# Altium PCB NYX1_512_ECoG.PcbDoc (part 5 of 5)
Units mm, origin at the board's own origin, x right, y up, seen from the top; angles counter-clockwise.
Board outline 46.64 x 13 mm, 4 copper layers (metal 2, via, metal1, electrodes), stack 0.007 mm thick; 9 components, 547 nets, 1871 pads, 0 vias.
Unrouted connection lines stored in the file: 652.
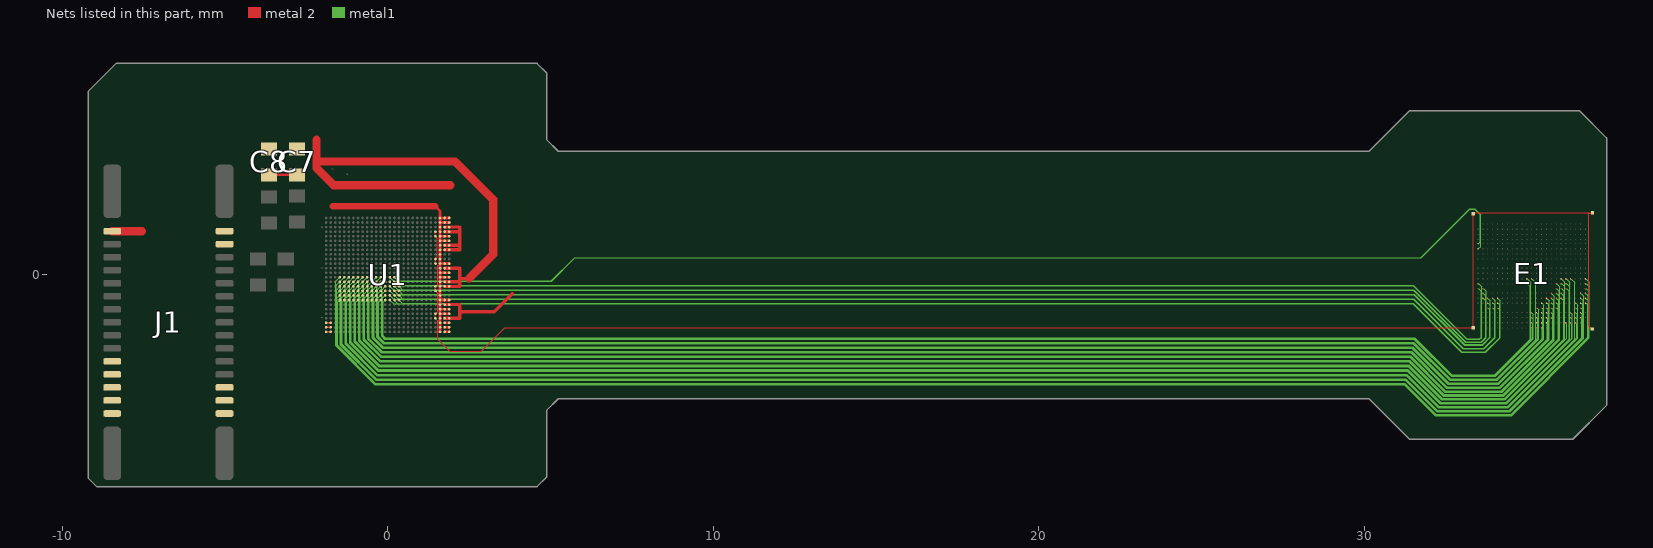
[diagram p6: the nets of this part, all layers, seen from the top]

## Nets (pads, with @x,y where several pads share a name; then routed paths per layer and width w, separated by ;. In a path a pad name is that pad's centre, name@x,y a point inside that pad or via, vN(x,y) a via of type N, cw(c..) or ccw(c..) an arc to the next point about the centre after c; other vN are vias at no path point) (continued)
el430: E1.364 pad.34@33.641,-0.725 U1.M16 | length 35.4
  metal 2 w0.012: pad.34@33.641,-0.725 E1.364@33.641,-0.706
  metal1 w0.005: U1.M16@0.35,-0.349 0.447,-0.446 30.141,-0.446 31.515,-0.446 33.113,-2.044 33.592,-2.044 33.721,-1.914 33.721,-0.786 33.66,-0.725 pad.34@33.641,-0.725
el431: E1.411 pad.34@33.791,-1.025 U1.M17 | length 35.2
  metal 2 w0.012: pad.34@33.791,-1.025 E1.411@33.791,-1.006
  metal1 w0.005: U1.M17@0.35,-0.489 0.447,-0.586 3.141,-0.586 31.528,-0.586 33.076,-2.134 33.629,-2.134 33.851,-1.912 33.851,-1.066 33.81,-1.025 pad.34@33.791,-1.025
el432: E1.412 pad.34@33.941,-1.025 U1.M18 | length 35.4
  metal 2 w0.012: pad.34@33.941,-1.025 E1.412@33.941,-1.006
  metal1 w0.005: U1.M18@0.35,-0.629 0.447,-0.726 3.141,-0.726 31.513,-0.726 33.031,-2.245 33.674,-2.245 34.001,-1.917 34.001,-1.066 33.96,-1.025 pad.34@33.941,-1.025
el433: E1.413 pad.34@34.091,-1.025 U1.M19 | length 35.6
  metal 2 w0.012: pad.34@34.091,-1.025 E1.413@34.091,-1.006
  metal1 w0.005: U1.M19@0.35,-0.769 0.447,-0.866 3.141,-0.866 30.141,-0.866 31.497,-0.866 32.987,-2.356 33.717,-2.356 34.151,-1.923 34.151,-1.066 34.11,-1.025 pad.34@34.091,-1.025
el434: E1.133 pad.34@33.491,0.814 U1.N14 | length 35.5
  metal 2 w0.012: E1.133@33.491,0.794 pad.34@33.491,0.814
  metal1 w0.005: U1.N14@0.21,-0.069 0.317,-0.176 5.033,-0.176 5.741,0.532 30.141,0.532 31.737,0.532 33.237,2.032 33.387,2.032 33.571,1.849 33.571,0.874 33.51,0.814 pad.34@33.491,0.814
el435: E1.317 pad.34@33.491,-0.425 U1.N15 | length 35.7
  metal 2 w0.012: pad.34@33.491,-0.425 E1.317@33.491,-0.406
  metal1 w0.005: U1.N15@0.21,-0.209 0.317,-0.316 5.05,-0.316 31.499,-0.316 33.145,-1.963 33.547,-1.963 33.591,-1.918 33.591,-0.506 33.51,-0.425 pad.34@33.491,-0.425
el436: E1.341 pad.34@33.641,-0.575 U1.N16 | length 35.7
  metal 2 w0.012: pad.34@33.641,-0.575 E1.341@33.641,-0.556
  metal1 w0.005: U1.N16@0.21,-0.349 0.317,-0.456 30.141,-0.456 31.511,-0.456 33.109,-2.054 33.596,-2.054 33.731,-1.918 33.731,-0.646 33.66,-0.575 pad.34@33.641,-0.575
el437: E1.388 pad.34@33.791,-0.875 U1.N17 | length 35.5
  metal 2 w0.012: pad.34@33.791,-0.875 E1.388@33.791,-0.856
  metal1 w0.005: U1.N17@0.21,-0.489 0.317,-0.596 3.141,-0.596 31.524,-0.596 33.071,-2.144 33.633,-2.144 33.861,-1.916 33.861,-0.926 33.81,-0.875 pad.34@33.791,-0.875
el438: E1.389 pad.34@33.941,-0.875 U1.N18 | length 35.7
  metal 2 w0.012: pad.34@33.941,-0.875 E1.389@33.941,-0.856
  metal1 w0.005: U1.N18@0.21,-0.629 0.317,-0.736 3.141,-0.736 31.508,-0.736 33.027,-2.255 33.678,-2.255 34.011,-1.921 34.011,-0.926 33.96,-0.875 pad.34@33.941,-0.875
el439: E1.390 pad.34@34.091,-0.875 U1.N19 | length 35.9
  metal 2 w0.012: pad.34@34.091,-0.875 E1.390@34.091,-0.856
  metal1 w0.005: U1.N19@0.21,-0.769 0.317,-0.876 3.141,-0.876 30.141,-0.876 31.493,-0.876 32.983,-2.366 33.722,-2.366 34.161,-1.927 34.161,-0.926 34.11,-0.875 pad.34@34.091,-0.875
el440: E1.110 pad.34@33.491,0.964 U1.P14 | length 35.5
  metal 2 w0.012: E1.110@33.491,0.944 pad.34@33.491,0.964
  metal1 w0.005: U1.P14@0.07,-0.069 0.188,-0.186 5.037,-0.186 5.745,0.522 30.141,0.522 31.742,0.522 33.242,2.022 33.383,2.022 33.561,1.845 33.561,1.014 33.51,0.964 pad.34@33.491,0.964
el441: E1.294 pad.34@33.491,-0.275 U1.P15 | length 36
  metal 2 w0.012: pad.34@33.491,-0.275 E1.294@33.491,-0.256
  metal1 w0.005: U1.P15@0.07,-0.209 0.188,-0.326 5.054,-0.326 31.494,-0.326 33.141,-1.973 33.551,-1.973 33.601,-1.923 33.601,-0.366 33.51,-0.275 pad.34@33.491,-0.275
el442: E1.318 pad.34@33.641,-0.425 U1.P16 | length 36
  metal 2 w0.012: pad.34@33.641,-0.425 E1.318@33.641,-0.406
  metal1 w0.005: U1.P16@0.07,-0.349 0.188,-0.466 31.507,-0.466 33.105,-2.064 33.6,-2.064 33.741,-1.923 33.741,-0.506 33.66,-0.425 pad.34@33.641,-0.425
el443: E1.365 pad.34@33.791,-0.725 U1.P17 | length 35.8
  metal 2 w0.012: pad.34@33.791,-0.725 E1.365@33.791,-0.706
  metal1 w0.005: U1.P17@0.07,-0.489 0.188,-0.606 3.141,-0.606 31.52,-0.606 33.067,-2.154 33.637,-2.154 33.871,-1.92 33.871,-0.786 33.81,-0.725 pad.34@33.791,-0.725
el444: E1.366 pad.34@33.941,-0.725 U1.P18 | length 36
  metal 2 w0.012: pad.34@33.941,-0.725 E1.366@33.941,-0.706
  metal1 w0.005: U1.P18@0.07,-0.629 0.188,-0.746 3.141,-0.746 31.504,-0.746 33.023,-2.265 33.682,-2.265 34.021,-1.925 34.021,-0.786 33.96,-0.725 pad.34@33.941,-0.725
el445: E1.367 pad.34@34.091,-0.725 U1.P19 | length 36.2
  metal 2 w0.012: pad.34@34.091,-0.725 E1.367@34.091,-0.706
  metal1 w0.005: U1.P19@0.07,-0.769 0.188,-0.886 3.141,-0.886 30.141,-0.886 31.489,-0.886 32.979,-2.376 33.726,-2.376 34.171,-1.931 34.171,-0.786 34.11,-0.725 pad.34@34.091,-0.725
el446: E1.443 pad.34@35.141,-1.175 U1.R14 | length 39.1
  metal 2 w0.012: pad.34@35.141,-1.175 E1.443@35.141,-1.156
  metal1 w0.005: U1.R14@-0.07,-0.069 -0.188,-0.186 -0.188,-1.883 -0.099,-1.971 29.641,-1.971 31.523,-1.971 32.668,-3.117 34.032,-3.117 35.191,-1.958 35.191,-1.206 35.16,-1.175 pad.34@35.141,-1.175
el447: E1.466 pad.34@35.141,-1.325 U1.R15 | length 38.7
  metal 2 w0.012: pad.34@35.141,-1.325 E1.466@35.141,-1.306
  metal1 w0.005: U1.R15@-0.07,-0.209 -0.178,-0.316 -0.178,-1.879 -0.095,-1.961 31.527,-1.961 32.672,-3.107 34.028,-3.107 35.181,-1.954 35.181,-1.346 35.16,-1.325 pad.34@35.141,-1.325
el448: E1.488 pad.34@35.141,-1.475 U1.R16 | length 38.4
  metal 2 w0.012: pad.34@35.141,-1.475 E1.488@35.141,-1.456
  metal1 w0.005: U1.R16@-0.07,-0.349 -0.168,-0.446 -0.168,-1.875 -0.091,-1.951 31.531,-1.951 32.676,-3.097 34.024,-3.097 35.171,-1.95 35.171,-1.505 pad.34@35.141,-1.475
el449: E1.508 pad.34@35.141,-1.625 U1.R17 | length 38.1
  metal 2 w0.012: pad.34@35.141,-1.625 E1.508@35.141,-1.606
  metal1 w0.005: U1.R17@-0.07,-0.489 -0.158,-0.576 -0.158,-1.871 -0.087,-1.941 31.535,-1.941 32.68,-3.087 34.02,-3.087 35.161,-1.945 35.161,-1.645 pad.34@35.141,-1.625
el450: E1.281 pad.34@34.991,-0.125 U1.R18 | length 39.4
  metal 2 w0.012: pad.34@34.991,-0.125 E1.281@34.991,-0.106
  metal1 w0.005: U1.R18@-0.07,-0.629 -0.148,-0.706 -0.148,-1.866 -0.083,-1.931 31.539,-1.931 32.685,-3.077 34.016,-3.077 35.111,-1.981 35.111,-0.226 35.01,-0.125 pad.34@34.991,-0.125
el451: E1.304 pad.34@34.991,-0.275 U1.R19 | length 39.1
  metal 2 w0.012: pad.34@34.991,-0.275 E1.304@34.991,-0.256
  metal1 w0.005: U1.R19@-0.07,-0.769 -0.138,-0.836 -0.138,-1.862 -0.079,-1.921 31.543,-1.921 32.689,-3.067 34.012,-3.067 35.101,-1.977 35.101,-0.366 35.01,-0.275 pad.34@34.991,-0.275
el452: E1.421 pad.34@35.291,-1.025 U1.T14 | length 39.6
  metal 2 w0.012: pad.34@35.291,-1.025 E1.421@35.291,-1.006
  metal1 w0.005: U1.T14@-0.21,-0.069 -0.328,-0.186 -0.328,-1.913 -0.129,-2.111 30.693,-2.111 31.491,-2.111 32.618,-3.238 34.081,-3.238 35.351,-1.968 35.351,-1.066 35.31,-1.025 pad.34@35.291,-1.025
el453: E1.444 pad.34@35.291,-1.175 U1.T15 | length 39.3
  metal 2 w0.012: pad.34@35.291,-1.175 E1.444@35.291,-1.156
  metal1 w0.005: U1.T15@-0.21,-0.209 -0.318,-0.316 -0.318,-1.909 -0.125,-2.101 30.697,-2.101 31.495,-2.101 32.622,-3.228 34.077,-3.228 35.341,-1.963 35.341,-1.206 35.31,-1.175 pad.34@35.291,-1.175
el454: E1.467 pad.34@35.291,-1.325 U1.T16 | length 39
  metal 2 w0.012: pad.34@35.291,-1.325 E1.467@35.291,-1.306
  metal1 w0.005: U1.T16@-0.21,-0.349 -0.308,-0.446 -0.308,-1.904 -0.121,-2.091 30.701,-2.091 31.499,-2.091 32.626,-3.218 34.073,-3.218 35.331,-1.959 35.331,-1.346 35.31,-1.325 pad.34@35.291,-1.325
el455: E1.489 pad.34@35.291,-1.475 U1.T17 | length 38.6
  metal 2 w0.012: pad.34@35.291,-1.475 E1.489@35.291,-1.456
  metal1 w0.005: U1.T17@-0.21,-0.489 -0.298,-0.576 -0.298,-1.9 -0.117,-2.081 30.705,-2.081 31.503,-2.081 32.63,-3.208 34.069,-3.208 35.321,-1.955 35.321,-1.505 pad.34@35.291,-1.475
el456: E1.509 pad.34@35.291,-1.625 U1.T18 | length 38.3
  metal 2 w0.012: pad.34@35.291,-1.625 E1.509@35.291,-1.606
  metal1 w0.005: U1.T18@-0.21,-0.629 -0.288,-0.706 -0.288,-1.896 -0.113,-2.071 30.709,-2.071 31.508,-2.071 32.634,-3.198 34.064,-3.198 35.311,-1.951 35.311,-1.645 pad.34@35.291,-1.625
el457: E1.282 pad.34@35.141,-0.125 U1.T19 | length 39.7
  metal 2 w0.012: pad.34@35.141,-0.125 E1.282@35.141,-0.106
  metal1 w0.005: U1.T19@-0.21,-0.769 -0.278,-0.836 -0.278,-1.892 -0.108,-2.061 31.512,-2.061 32.637,-3.187 34.061,-3.187 35.261,-1.987 35.261,-0.226 35.16,-0.125 pad.34@35.141,-0.125
el458: E1.399 pad.34@35.441,-0.875 U1.U14 | length 40.2
  metal 2 w0.012: pad.34@35.441,-0.875 E1.399@35.441,-0.856
  metal1 w0.005: U1.U14@-0.35,-0.069 -0.468,-0.186 -0.468,-1.942 -0.158,-2.252 31.46,-2.252 32.567,-3.358 34.13,-3.358 35.511,-1.977 35.511,-0.926 35.46,-0.875 pad.34@35.441,-0.875
el459: E1.422 pad.34@35.441,-1.025 U1.U15 | length 39.9
  metal 2 w0.012: pad.34@35.441,-1.025 E1.422@35.441,-1.006
  metal1 w0.005: U1.U15@-0.35,-0.209 -0.458,-0.316 -0.458,-1.938 -0.154,-2.242 31.464,-2.242 32.571,-3.348 34.126,-3.348 35.501,-1.973 35.501,-1.066 35.46,-1.025 pad.34@35.441,-1.025
el460: E1.445 pad.34@35.441,-1.175 U1.U16 | length 39.6
  metal 2 w0.012: pad.34@35.441,-1.175 E1.445@35.441,-1.156
  metal1 w0.005: U1.U16@-0.35,-0.349 -0.448,-0.446 -0.448,-1.934 -0.15,-2.232 31.468,-2.232 32.575,-3.338 34.122,-3.338 35.491,-1.969 35.491,-1.206 35.46,-1.175 pad.34@35.441,-1.175
el461: E1.468 pad.34@35.441,-1.325 U1.U17 | length 39.2
  metal 2 w0.012: pad.34@35.441,-1.325 E1.468@35.441,-1.306
  metal1 w0.005: U1.U17@-0.35,-0.489 -0.438,-0.576 -0.438,-1.93 -0.146,-2.222 31.472,-2.222 32.579,-3.328 34.117,-3.328 35.481,-1.965 35.481,-1.346 35.46,-1.325 pad.34@35.441,-1.325
el462: E1.490 pad.34@35.441,-1.475 U1.U18 | length 38.9
  metal 2 w0.012: pad.34@35.441,-1.475 E1.490@35.441,-1.456
  metal1 w0.005: U1.U18@-0.35,-0.629 -0.428,-0.706 -0.428,-1.926 -0.142,-2.212 31.478,-2.212 32.584,-3.318 34.114,-3.318 35.471,-1.961 35.471,-1.505 pad.34@35.441,-1.475
el463: E1.510 pad.34@35.441,-1.625 U1.U19 | length 38.6
  metal 2 w0.012: pad.34@35.441,-1.625 E1.510@35.441,-1.606
  metal1 w0.005: U1.U19@-0.35,-0.769 -0.418,-0.836 -0.418,-1.922 -0.138,-2.202 30.567,-2.202 31.482,-2.202 32.588,-3.308 34.11,-3.308 35.461,-1.957 35.461,-1.645 pad.34@35.441,-1.625
el464: E1.377 pad.34@35.591,-0.725 U1.V14 | length 40.8
  metal 2 w0.012: pad.34@35.591,-0.725 E1.377@35.591,-0.706
  metal1 w0.005: U1.V14@-0.49,-0.069 -0.608,-0.186 -0.608,-1.972 -0.189,-2.391 30.633,-2.391 ; 30.637,-2.391 31.43,-2.391 32.517,-3.478 34.18,-3.478 35.671,-1.987 35.671,-0.786 35.61,-0.725 pad.34@35.591,-0.725
el465: E1.400 pad.34@35.591,-0.875 U1.V15 | length 40.5
  metal 2 w0.012: pad.34@35.591,-0.875 E1.400@35.591,-0.856
  metal1 w0.005: U1.V15@-0.49,-0.209 -0.598,-0.316 -0.598,-1.968 -0.185,-2.381 30.637,-2.381 ; 30.641,-2.381 31.434,-2.381 32.521,-3.468 34.175,-3.468 35.661,-1.983 35.661,-0.926 35.61,-0.875 pad.34@35.591,-0.875
el466: E1.423 pad.34@35.591,-1.025 U1.V16 | length 40.1
  metal 2 w0.012: pad.34@35.591,-1.025 E1.423@35.591,-1.006
  metal1 w0.005: U1.V16@-0.49,-0.349 -0.588,-0.446 -0.588,-1.964 -0.18,-2.371 31.438,-2.371 32.525,-3.458 34.171,-3.458 35.651,-1.979 35.651,-1.066 35.61,-1.025 pad.34@35.591,-1.025
el467: E1.446 pad.34@35.591,-1.175 U1.V17 | length 39.8
  metal 2 w0.012: pad.34@35.591,-1.175 E1.446@35.591,-1.156
  metal1 w0.005: U1.V17@-0.49,-0.489 -0.578,-0.576 -0.578,-1.96 -0.176,-2.361 31.442,-2.361 32.529,-3.448 34.167,-3.448 35.641,-1.975 35.641,-1.206 35.61,-1.175 pad.34@35.591,-1.175
el468: E1.469 pad.34@35.591,-1.325 U1.V18 | length 39.5
  metal 2 w0.012: pad.34@35.591,-1.325 E1.469@35.591,-1.306
  metal1 w0.005: U1.V18@-0.49,-0.629 -0.568,-0.706 -0.568,-1.956 -0.172,-2.351 31.446,-2.351 32.533,-3.438 34.163,-3.438 35.631,-1.97 35.631,-1.346 35.61,-1.325 pad.34@35.591,-1.325
el469: E1.491 pad.34@35.591,-1.475 U1.V19 | length 39.1
  metal 2 w0.012: pad.34@35.591,-1.475 E1.491@35.591,-1.456
  metal1 w0.005: U1.V19@-0.49,-0.769 -0.558,-0.836 -0.558,-1.952 -0.168,-2.341 31.45,-2.341 32.538,-3.428 34.159,-3.428 35.621,-1.966 35.621,-1.505 pad.34@35.591,-1.475
el470: E1.355 pad.34@35.741,-0.575 U1.W14 | length 41.4
  metal 2 w0.012: pad.34@35.741,-0.575 E1.355@35.741,-0.556
  metal1 w0.005: U1.W14@-0.63,-0.069 -0.748,-0.186 -0.748,-2.002 -0.218,-2.531 30.603,-2.531 ; 30.607,-2.531 31.4,-2.531 32.467,-3.599 34.229,-3.599 35.831,-1.997 35.831,-0.646 35.76,-0.575 pad.34@35.741,-0.575
el471: E1.378 pad.34@35.741,-0.725 U1.W15 | length 41
  metal 2 w0.012: pad.34@35.741,-0.725 E1.378@35.741,-0.706
  metal1 w0.005: U1.W15@-0.63,-0.209 -0.738,-0.316 -0.738,-1.998 -0.214,-2.521 31.404,-2.521 32.471,-3.588 34.225,-3.588 35.821,-1.993 35.821,-0.786 35.76,-0.725 pad.34@35.741,-0.725
el472: E1.401 pad.34@35.741,-0.875 U1.W16 | length 40.7
  metal 2 w0.012: pad.34@35.741,-0.875 E1.401@35.741,-0.856
  metal1 w0.005: U1.W16@-0.63,-0.349 -0.728,-0.446 -0.728,-1.994 -0.21,-2.511 31.408,-2.511 32.475,-3.578 34.221,-3.578 35.811,-1.988 35.811,-0.926 35.76,-0.875 pad.34@35.741,-0.875
el473: E1.424 pad.34@35.741,-1.025 U1.W17 | length 40.4
  metal 2 w0.012: pad.34@35.741,-1.025 E1.424@35.741,-1.006
  metal1 w0.005: U1.W17@-0.63,-0.489 -0.718,-0.576 -0.718,-1.99 -0.206,-2.501 31.412,-2.501 32.48,-3.568 34.217,-3.568 35.801,-1.984 35.801,-1.066 35.76,-1.025 pad.34@35.741,-1.025
el474: E1.447 pad.34@35.741,-1.175 U1.W18 | length 40
  metal 2 w0.012: pad.34@35.741,-1.175 E1.447@35.741,-1.156
  metal1 w0.005: U1.W18@-0.63,-0.629 -0.708,-0.706 -0.708,-1.985 -0.202,-2.491 31.416,-2.491 32.484,-3.558 34.213,-3.558 35.791,-1.98 35.791,-1.206 35.76,-1.175 pad.34@35.741,-1.175
el475: E1.470 pad.34@35.741,-1.325 U1.W19 | length 39.7
  metal 2 w0.012: pad.34@35.741,-1.325 E1.470@35.741,-1.306
  metal1 w0.005: U1.W19@-0.63,-0.769 -0.698,-0.836 -0.698,-1.981 -0.198,-2.481 31.42,-2.481 32.488,-3.548 34.209,-3.548 35.781,-1.976 35.781,-1.346 35.76,-1.325 pad.34@35.741,-1.325
el476: E1.310 pad.34@35.891,-0.275 U1.Y14 | length 42.1
  metal 2 w0.012: pad.34@35.891,-0.275 E1.310@35.891,-0.256
  metal1 w0.005: U1.Y14@-0.77,-0.069 -0.888,-0.186 -0.888,-2.032 -0.248,-2.671 31.37,-2.671 32.417,-3.719 34.279,-3.719 36.001,-1.997 36.001,-0.366 35.91,-0.275 pad.34@35.891,-0.275
el477: E1.333 pad.34@35.891,-0.425 U1.Y15 | length 41.8
  metal 2 w0.012: pad.34@35.891,-0.425 E1.333@35.891,-0.406
  metal1 w0.005: U1.Y15@-0.77,-0.209 -0.878,-0.316 -0.878,-2.028 -0.244,-2.661 31.374,-2.661 32.422,-3.709 34.275,-3.709 35.991,-1.992 35.991,-0.506 35.91,-0.425 pad.34@35.891,-0.425
el478: E1.356 pad.34@35.891,-0.575 U1.Y16 | length 41.4
  metal 2 w0.012: pad.34@35.891,-0.575 E1.356@35.891,-0.556
  metal1 w0.005: U1.Y16@-0.77,-0.349 -0.868,-0.446 -0.868,-2.023 -0.24,-2.651 31.378,-2.651 32.426,-3.699 34.271,-3.699 35.981,-1.988 35.981,-0.646 35.91,-0.575 pad.34@35.891,-0.575
el479: E1.379 pad.34@35.891,-0.725 U1.Y17 | length 41.1
  metal 2 w0.012: pad.34@35.891,-0.725 E1.379@35.891,-0.706
  metal1 w0.005: U1.Y17@-0.77,-0.489 -0.858,-0.576 -0.858,-2.019 -0.236,-2.641 31.382,-2.641 32.43,-3.689 34.267,-3.689 35.971,-1.984 35.971,-0.786 35.91,-0.725 pad.34@35.891,-0.725
el480: E1.402 pad.34@35.891,-0.875 U1.Y18 | length 40.8
  metal 2 w0.012: pad.34@35.891,-0.875 E1.402@35.891,-0.856
  metal1 w0.005: U1.Y18@-0.77,-0.629 -0.848,-0.706 -0.848,-2.015 -0.232,-2.631 31.387,-2.631 32.434,-3.679 34.262,-3.679 35.961,-1.98 35.961,-0.926 35.91,-0.875 pad.34@35.891,-0.875
el481: E1.425 pad.34@35.891,-1.025 U1.Y19 | length 40.5
  metal 2 w0.012: pad.34@35.891,-1.025 E1.425@35.891,-1.006
  metal1 w0.005: U1.Y19@-0.77,-0.769 -0.838,-0.836 -0.838,-2.011 -0.227,-2.621 31.391,-2.621 32.438,-3.669 34.258,-3.669 35.951,-1.976 35.951,-1.066 35.91,-1.025 pad.34@35.891,-1.025
el482: E1.495 pad.34@36.191,-1.475 U1.AA14 | length 41.3
  metal 2 w0.012: pad.34@36.191,-1.475 E1.495@36.191,-1.456
  metal1 w0.005: U1.AA14@-0.91,-0.069 -1.028,-0.186 -1.028,-2.061 -0.278,-2.811 3.141,-2.811 29.629,-2.811 31.34,-2.811 32.369,-3.84 34.328,-3.84 36.221,-1.946 36.221,-1.505 pad.34@36.191,-1.475
el483: E1.288 pad.34@36.041,-0.125 U1.AA15 | length 42.5
  metal 2 w0.012: pad.34@36.041,-0.125 E1.288@36.041,-0.106
  metal1 w0.005: U1.AA15@-0.91,-0.209 -1.018,-0.316 -1.018,-2.057 -0.274,-2.801 31.344,-2.801 32.372,-3.829 34.325,-3.829 36.161,-1.992 36.161,-0.226 36.06,-0.125 pad.34@36.041,-0.125
el484: E1.311 pad.34@36.041,-0.275 U1.AA16 | length 42.2
  metal 2 w0.012: pad.34@36.041,-0.275 E1.311@36.041,-0.256
  metal1 w0.005: U1.AA16@-0.91,-0.349 -1.008,-0.446 -1.008,-2.053 -0.27,-2.791 30.551,-2.791 31.349,-2.791 32.376,-3.819 34.32,-3.819 36.151,-1.988 36.151,-0.366 36.06,-0.275 pad.34@36.041,-0.275
el485: E1.334 pad.34@36.041,-0.425 U1.AA17 | length 41.9
  metal 2 w0.012: pad.34@36.041,-0.425 E1.334@36.041,-0.406
  metal1 w0.005: U1.AA17@-0.91,-0.489 -0.998,-0.576 -0.998,-2.049 -0.265,-2.781 30.555,-2.781 ; 30.551,-2.781 31.353,-2.781 32.38,-3.809 34.316,-3.809 36.141,-1.984 36.141,-0.506 36.06,-0.425 pad.34@36.041,-0.425
el486: E1.357 pad.34@36.041,-0.575 U1.AA18 | length 41.5
  metal 2 w0.012: pad.34@36.041,-0.575 E1.357@36.041,-0.556
  metal1 w0.005: U1.AA18@-0.91,-0.629 -0.988,-0.706 -0.988,-2.045 -0.261,-2.771 30.559,-2.771 31.357,-2.771 32.384,-3.799 34.312,-3.799 36.131,-1.98 36.131,-0.646 36.06,-0.575 pad.34@36.041,-0.575
el487: E1.380 pad.34@36.041,-0.725 U1.AA19 | length 41.2
  metal 2 w0.012: pad.34@36.041,-0.725 E1.380@36.041,-0.706
  metal1 w0.005: U1.AA19@-0.91,-0.769 -0.978,-0.836 -0.978,-2.041 -0.257,-2.761 30.563,-2.761 ; 30.559,-2.761 31.361,-2.761 32.388,-3.789 34.308,-3.789 36.121,-1.976 36.121,-0.786 36.06,-0.725 pad.34@36.041,-0.725
el488: E1.451 pad.34@36.341,-1.175 U1.AB14 | length 42.1
  metal 2 w0.012: pad.34@36.341,-1.175 E1.451@36.341,-1.156
  metal1 w0.005: U1.AB14@-1.05,-0.069 -1.168,-0.186 -1.168,-2.091 -0.308,-2.951 3.141,-2.951 29.641,-2.951 30.481,-2.951 31.311,-2.951 32.319,-3.96 34.377,-3.96 36.391,-1.946 36.391,-1.206 36.36,-1.175 pad.34@36.341,-1.175
el489: E1.474 pad.34@36.341,-1.325 U1.AB15 | length 41.7
  metal 2 w0.012: pad.34@36.341,-1.325 E1.474@36.341,-1.306
  metal1 w0.005: U1.AB15@-1.05,-0.209 -1.158,-0.316 -1.158,-2.087 -0.304,-2.941 3.141,-2.941 29.641,-2.941 30.485,-2.941 31.315,-2.941 32.323,-3.95 34.373,-3.95 36.381,-1.942 36.381,-1.346 ; pad.34@36.341,-1.325 36.36,-1.325 36.381,-1.345
el490: E1.496 pad.34@36.341,-1.475 U1.AB16 | length 41.4
  metal 2 w0.012: pad.34@36.341,-1.475 E1.496@36.341,-1.456
  metal1 w0.005: U1.AB16@-1.05,-0.349 -1.148,-0.446 -1.148,-2.083 -0.299,-2.931 3.141,-2.931 29.641,-2.931 31.319,-2.931 32.327,-3.94 34.369,-3.94 36.371,-1.938 36.371,-1.505 pad.34@36.341,-1.475
el491: E1.289 pad.34@36.191,-0.125 U1.AB17 | length 42.6
  metal 2 w0.012: pad.34@36.191,-0.125 E1.289@36.191,-0.106
  metal1 w0.005: U1.AB17@-1.05,-0.489 -1.138,-0.576 -1.138,-2.079 -0.295,-2.921 3.141,-2.921 29.641,-2.921 31.323,-2.921 32.331,-3.93 34.365,-3.93 36.311,-1.984 36.311,-0.226 36.21,-0.125 pad.34@36.191,-0.125
el492: E1.312 pad.34@36.191,-0.275 U1.AB18 | length 42.3
  metal 2 w0.012: pad.34@36.191,-0.275 E1.312@36.191,-0.256
  metal1 w0.005: U1.AB18@-1.05,-0.629 -1.128,-0.706 -1.128,-2.075 -0.291,-2.911 3.141,-2.911 29.641,-2.911 31.327,-2.911 32.336,-3.92 34.361,-3.92 36.301,-1.979 36.301,-0.366 36.21,-0.275 pad.34@36.191,-0.275
el493: E1.335 pad.34@36.191,-0.425 U1.AB19 | length 41.9
  metal 2 w0.012: pad.34@36.191,-0.425 E1.335@36.191,-0.406
  metal1 w0.005: U1.AB19@-1.05,-0.769 -1.118,-0.836 -1.118,-2.07 -0.287,-2.901 3.141,-2.901 29.641,-2.901 31.331,-2.901 32.34,-3.91 34.357,-3.91 36.291,-1.975 36.291,-0.506 36.21,-0.425 pad.34@36.191,-0.425
el494: E1.406 pad.34@36.491,-0.875 U1.AC14 | length 42.8
  metal 2 w0.012: pad.34@36.491,-0.875 E1.406@36.491,-0.856
  metal1 w0.005: U1.AC14@-1.19,-0.069 -1.308,-0.186 -1.308,-2.121 -0.337,-3.091 3.141,-3.091 29.641,-3.091 31.281,-3.091 32.27,-4.08 34.426,-4.08 36.561,-1.946 36.561,-0.926 36.51,-0.875 pad.34@36.491,-0.875
el495: E1.429 pad.34@36.491,-1.025 U1.AC15 | length 42.5
  metal 2 w0.012: pad.34@36.491,-1.025 E1.429@36.491,-1.006
  metal1 w0.005: U1.AC15@-1.19,-0.209 -1.298,-0.316 -1.298,-2.117 -0.333,-3.081 3.141,-3.081 29.641,-3.081 31.285,-3.081 32.274,-4.07 34.422,-4.07 36.551,-1.942 36.551,-1.066 36.51,-1.025 pad.34@36.491,-1.025
el496: E1.452 pad.34@36.491,-1.175 U1.AC16 | length 42.1
  metal 2 w0.012: pad.34@36.491,-1.175 E1.452@36.491,-1.156
  metal1 w0.005: U1.AC16@-1.19,-0.349 -1.288,-0.446 -1.288,-2.113 -0.329,-3.071 3.141,-3.071 29.641,-3.071 31.289,-3.071 32.278,-4.06 34.418,-4.06 36.541,-1.937 36.541,-1.206 36.51,-1.175 pad.34@36.491,-1.175
el497: E1.475 pad.34@36.491,-1.325 U1.AC17 | length 41.8
  metal 2 w0.012: pad.34@36.491,-1.325 E1.475@36.491,-1.306
  metal1 w0.005: U1.AC17@-1.19,-0.489 -1.278,-0.576 -1.278,-2.109 -0.325,-3.061 3.141,-3.061 29.641,-3.061 31.293,-3.061 32.283,-4.05 34.414,-4.05 36.531,-1.933 36.531,-1.346 36.51,-1.325 pad.34@36.491,-1.325
el498: E1.497 pad.34@36.491,-1.475 U1.AC18 | length 41.5
  metal 2 w0.012: pad.34@36.491,-1.475 E1.497@36.491,-1.456
  metal1 w0.005: U1.AC18@-1.19,-0.629 -1.268,-0.706 -1.268,-2.104 -0.321,-3.051 3.141,-3.051 29.641,-3.051 31.297,-3.051 32.287,-4.04 34.41,-4.04 36.521,-1.929 36.521,-1.505 pad.34@36.491,-1.475
el499: E1.290 pad.34@36.341,-0.125 U1.AC19 | length 42.7
  metal 2 w0.012: pad.34@36.341,-0.125 E1.290@36.341,-0.106
  metal1 w0.005: U1.AC19@-1.19,-0.769 -1.258,-0.836 -1.258,-2.1 -0.317,-3.041 31.301,-3.041 32.29,-4.03 34.406,-4.03 36.461,-1.975 36.461,-0.226 36.36,-0.125 pad.34@36.341,-0.125
el500: E1.361 pad.34@36.641,-0.575 U1.AD14 | length 43.5
  metal 2 w0.012: pad.34@36.641,-0.575 E1.361@36.641,-0.556
  metal1 w0.005: U1.AD14@-1.33,-0.069 -1.448,-0.186 -1.448,-2.151 -0.367,-3.231 31.251,-3.231 32.22,-4.201 34.476,-4.201 36.731,-1.945 36.731,-0.646 36.66,-0.575 pad.34@36.641,-0.575
el501: E1.384 pad.34@36.641,-0.725 U1.AD15 | length 43.2
  metal 2 w0.012: pad.34@36.641,-0.725 E1.384@36.641,-0.706
  metal1 w0.005: U1.AD15@-1.33,-0.209 -1.438,-0.316 -1.438,-2.147 -0.363,-3.221 31.255,-3.221 32.225,-4.191 34.472,-4.191 36.721,-1.941 36.721,-0.786 36.66,-0.725 pad.34@36.641,-0.725
el502: E1.407 pad.34@36.641,-0.875 U1.AD16 | length 42.9
  metal 2 w0.012: pad.34@36.641,-0.875 E1.407@36.641,-0.856
  metal1 w0.005: U1.AD16@-1.33,-0.349 -1.428,-0.446 -1.428,-2.142 -0.359,-3.211 31.259,-3.211 32.229,-4.181 34.468,-4.181 36.711,-1.937 36.711,-0.926 36.66,-0.875 pad.34@36.641,-0.875
el503: E1.430 pad.34@36.641,-1.025 U1.AD17 | length 42.5
  metal 2 w0.012: pad.34@36.641,-1.025 E1.430@36.641,-1.006
  metal1 w0.005: U1.AD17@-1.33,-0.489 -1.418,-0.576 -1.418,-2.138 -0.355,-3.201 31.263,-3.201 32.233,-4.171 34.464,-4.171 36.701,-1.933 36.701,-1.066 36.66,-1.025 pad.34@36.641,-1.025
el504: E1.453 pad.34@36.641,-1.175 U1.AD18 | length 42.2
  metal 2 w0.012: pad.34@36.641,-1.175 E1.453@36.641,-1.156
  metal1 w0.005: U1.AD18@-1.33,-0.629 -1.408,-0.706 -1.408,-2.134 -0.351,-3.191 31.268,-3.191 32.237,-4.161 34.459,-4.161 36.691,-1.929 36.691,-1.206 36.66,-1.175 pad.34@36.641,-1.175
el505: E1.476 pad.34@36.641,-1.325 U1.AD19 | length 41.9
  metal 2 w0.012: pad.34@36.641,-1.325 E1.476@36.641,-1.306
  metal1 w0.005: U1.AD19@-1.33,-0.769 -1.398,-0.836 -1.398,-2.13 -0.346,-3.181 31.272,-3.181 32.241,-4.151 34.455,-4.151 36.681,-1.925 36.681,-1.346 36.66,-1.325 pad.34@36.641,-1.325
el506: E1.293 pad.34@36.791,-0.125 U1.AE14 | length 44.4
  metal 2 w0.012: pad.34@36.791,-0.125 E1.293@36.791,-0.106
  metal1 w0.005: U1.AE14@-1.47,-0.069 -1.588,-0.186 -1.588,-2.18 -0.397,-3.371 31.221,-3.371 32.171,-4.321 34.526,-4.321 36.911,-1.935 36.911,-0.226 36.81,-0.125 pad.34@36.791,-0.125
el507: E1.316 pad.34@36.791,-0.275 U1.AE15 | length 44.1
  metal 2 w0.012: pad.34@36.791,-0.275 E1.316@36.791,-0.256
  metal1 w0.005: U1.AE15@-1.47,-0.209 -1.578,-0.316 -1.578,-2.176 -0.393,-3.361 3.141,-3.361 29.554,-3.361 31.225,-3.361 32.175,-4.311 34.522,-4.311 36.901,-1.931 36.901,-0.366 36.81,-0.275 pad.34@36.791,-0.275
el508: E1.339 pad.34@36.791,-0.425 U1.AE16 | length 43.8
  metal 2 w0.012: pad.34@36.791,-0.425 E1.339@36.791,-0.406
  metal1 w0.005: U1.AE16@-1.47,-0.349 -1.568,-0.446 -1.568,-2.172 -0.389,-3.351 3.141,-3.351 29.558,-3.351 31.23,-3.351 32.179,-4.301 34.517,-4.301 36.891,-1.927 36.891,-0.506 36.81,-0.425 pad.34@36.791,-0.425
el509: E1.362 pad.34@36.791,-0.575 U1.AE17 | length 43.4
  metal 2 w0.012: pad.34@36.791,-0.575 E1.362@36.791,-0.556
  metal1 w0.005: U1.AE17@-1.47,-0.489 -1.558,-0.576 -1.558,-2.168 -0.384,-3.341 3.141,-3.341 29.562,-3.341 31.234,-3.341 32.183,-4.291 34.513,-4.291 36.881,-1.923 36.881,-0.646 36.81,-0.575 pad.34@36.791,-0.575
el510: E1.385 pad.34@36.791,-0.725 U1.AE18 | length 43.1
  metal 2 w0.012: pad.34@36.791,-0.725 E1.385@36.791,-0.706
  metal1 w0.005: U1.AE18@-1.47,-0.629 -1.548,-0.706 -1.548,-2.164 -0.38,-3.331 3.141,-3.331 29.566,-3.331 31.238,-3.331 32.187,-4.281 34.509,-4.281 36.871,-1.919 36.871,-0.786 36.81,-0.725 pad.34@36.791,-0.725
el511: E1.408 pad.34@36.791,-0.875 U1.AE19 | length 42.8
  metal 2 w0.012: pad.34@36.791,-0.875 E1.408@36.791,-0.856
  metal1 w0.005: U1.AE19@-1.47,-0.769 -1.538,-0.836 -1.538,-2.16 -0.376,-3.321 3.141,-3.321 29.571,-3.321 31.242,-3.321 32.191,-4.271 34.505,-4.271 36.861,-1.915 36.861,-0.926 36.81,-0.875 pad.34@36.791,-0.875
GND: J1.28
MUX01_CS: J1.27
MUX01_MISO: J1.23
MUX01_MOSI: J1.25
MUX01_RES: J1.29
MUX01_SCLK: J1.21
NetU1_A24: U1.A24 U1.B24 | length 0.1
  metal 2 w0.08: U1.B24@1.75,-1.469 U1.A24@1.89,-1.469
NetU1_A25: U1.A25 U1.B25 | length 0.1
  metal 2 w0.08: U1.B25@1.75,-1.609 U1.A25@1.89,-1.609
NetU1_A26: U1.A26 U1.B26 | length 0.1
  metal 2 w0.08: U1.B26@1.75,-1.749 U1.A26@1.89,-1.749
NetU1_AG24: U1.AG24 U1.AH24 | length 0.1
  metal 2 w0.05: U1.AH24@-1.89,-1.469 U1.AG24@-1.75,-1.469
NetU1_AG25: U1.AG25 U1.AH25 | length 0.1
  metal 2 w0.05: U1.AH25@-1.89,-1.609 U1.AG25@-1.75,-1.609
NetU1_AG26: U1.AG26 U1.AH26 | length 0.1
  metal 2 w0.05: U1.AH26@-1.89,-1.749 U1.AG26@-1.75,-1.749
REF: pad.28 U1.D4 U1.D5 U1.D10 U1.D11 U1.D16 U1.D17 U1.D22 U1.D23 | length 46.6
  metal 2 w0.02: U1.D4@1.47,1.331 U1.D5@1.47,1.191 1.47,1.188 1.529,1.129 1.529,0.55 U1.D10@1.47,0.491 U1.D11@1.47,0.351 1.537,0.284 1.537,-0.282 U1.D16@1.47,-0.349 U1.D17@1.47,-0.489 1.541,-0.56 1.541,-1.126 1.479,-1.189 U1.D22@1.47,-1.189 U1.D23@1.47,-1.329 1.47,-1.337 1.54,-1.407 1.54,-1.979 1.905,-2.344 2.879,-2.344 3.604,-1.619 pad.28@33.341,-1.619 pad.28@33.341,1.877 33.372,1.908 pad.28@37.005,1.908 36.988,1.891 36.908,1.891 36.896,1.88 36.896,-1.575 36.937,-1.616 36.957,-1.616 pad.28@36.997,-1.656
VCC_1V8: J1.30
VCC_2V5: C7.1 C8.1 J1.1 U1.A3 U1.A4 U1.A7 U1.A8 U1.A12 U1.A15 U1.A16 U1.A20 U1.A23 U1.B3 U1.B4 U1.B7 U1.B8 U1.B12 U1.B15 U1.B16 U1.B20 U1.B23 | length 22.8
  metal 2 w0.1: C8.1@-3.644,3.87 C8.1@-3.624,3.85 ; U1.B23@1.75,-1.329 U1.A23@1.89,-1.329 2.215,-1.329 2.215,-1.131 ; U1.B20@1.75,-0.909 U1.A20@1.89,-0.909 2.215,-0.909 2.215,-1.131 ; U1.B16@1.75,-0.35 1.89,-0.35 2.215,-0.35 2.215,-0.21 ; U1.B15@1.75,-0.21 1.89,-0.21 2.215,-0.21 ; U1.B12@1.75,0.211 U1.A12@1.89,0.211 2.215,0.21 2.215,-0.108 ; U1.B8@1.75,0.771 U1.A8@1.89,0.771 2.215,0.771 2.215,0.911 ; U1.B7@1.75,0.911 U1.A7@1.89,0.911 2.215,0.911 ; U1.B4@1.75,1.331 U1.A4@1.89,1.331 2.215,1.331 ; U1.B3@1.75,1.471 U1.A3@1.89,1.471 2.211,1.471 ; 2.215,1.466 2.215,1.331 ; 2.501,-0.108 2.215,-0.108 ; 3.829,-0.573 3.271,-1.131 2.215,-1.131 ; 2.215,-0.21 2.215,-0.108 ; 2.215,0.911 2.215,1.331
  metal 2 w0.254: J1.1@-8.459,1.346 -7.549,1.346 -7.544,1.341 ; -2.187,4.155 -2.187,3.488 ; 1.933,2.758 -1.66,2.758 -2.187,3.285 -2.187,3.488 ; 2.501,-0.108 3.241,0.632 3.241,2.319 2.072,3.488 -2.187,3.488
VDD_5V: J1.26
VSSA: C7.2 C8.2 J1.2 J1.4 U1.A1 U1.A2 U1.A5 U1.A6 U1.A11 U1.A13 U1.A14 U1.A19 U1.A21 U1.A22 U1.B1 U1.B2 U1.B5 U1.B6 U1.B11 U1.B13 U1.B14 U1.B19 U1.B21 U1.B22 U1.C1 U1.C2 U1.C3 U1.C4 U1.C5 U1.C6 U1.C7 U1.C8 U1.C9 U1.C10 U1.C11 U1.C12 U1.C13 U1.C14 U1.C15 U1.C16 U1.C17 U1.C18 U1.C19 U1.C20 U1.C21 U1.C22 U1.C23 U1.C24 U1.C25 U1.C26 | length 10.9
  metal 2 w0.08: C8.2@-3.698,3.088 -3.686,3.076 C7.2@-2.786,3.076 C7.2@-2.732,3.076 ; 1.465,2.105 1.61,1.96 U1.C1@1.61,1.751 ; U1.C26@1.61,-1.749 U1.C25@1.61,-1.609 U1.C24@1.61,-1.469 U1.C23@1.61,-1.329 U1.C22@1.61,-1.189 ; U1.A22@1.89,-1.189 U1.B22@1.75,-1.189 U1.C22@1.61,-1.189 ; U1.A21@1.89,-1.049 U1.B21@1.75,-1.049 U1.C21@1.61,-1.049 ; U1.A19@1.89,-0.769 1.75,-0.769 U1.C19@1.61,-0.769 ; U1.A14@1.89,-0.069 U1.B14@1.75,-0.069 U1.C14@1.61,-0.069 ; U1.A13@1.89,0.071 U1.B13@1.75,0.071 U1.C13@1.61,0.071 ; U1.A11@1.89,0.351 U1.B11@1.75,0.351 U1.C11@1.61,0.351 ; U1.A6@1.89,1.051 U1.B6@1.75,1.051 U1.C6@1.61,1.051 ; U1.A5@1.89,1.191 U1.B5@1.75,1.191 U1.C5@1.61,1.191 ; U1.A2@1.89,1.611 1.75,1.611 U1.C2@1.61,1.611 ; U1.A1@1.89,1.751 U1.B1@1.75,1.751 U1.C1@1.61,1.751 ; U1.C22@1.61,-1.189 U1.C21@1.61,-1.049 ; U1.C21@1.61,-1.049 U1.C20@1.61,-0.909 U1.C19@1.61,-0.769 ; U1.C19@1.61,-0.769 U1.C18@1.61,-0.629 U1.C17@1.61,-0.489 U1.C16@1.61,-0.349 U1.C15@1.61,-0.209 U1.C14@1.61,-0.069 ; U1.C14@1.61,-0.069 U1.C13@1.61,0.071 ; U1.C13@1.61,0.071 U1.C12@1.61,0.211 U1.C11@1.61,0.351 ; U1.C11@1.61,0.351 U1.C10@1.61,0.491 U1.C9@1.61,0.631 U1.C8@1.61,0.771 U1.C7@1.61,0.911 U1.C6@1.61,1.051 ; U1.C6@1.61,1.051 U1.C5@1.61,1.191 ; U1.C5@1.61,1.191 U1.C4@1.61,1.331 U1.C3@1.61,1.471 U1.C2@1.61,1.611 ; U1.C2@1.61,1.611 U1.C1@1.61,1.751
  metal 2 w0.1: C8.2@-3.698,3.07 C8.2@-3.644,3.07
  metal 2 w0.2: -1.687,2.105 1.465,2.105
pads on no net: J1.31 J1.32 J1.33 J1.34 U1.AA1 U1.AA26 U1.AB1 U1.AB26 U1.AC1 U1.AC26 U1.AD1 U1.AD26 U1.AE1 U1.AE26 U1.D1 U1.D26 U1.E1 U1.E4 U1.E5 U1.E10 U1.E11 U1.E16 U1.E17 U1.E22 U1.E23 U1.E26 U1.F1 U1.F26 U1.G1 U1.G26 U1.H1 U1.H26 U1.J1 U1.J26 U1.K1 U1.K26 U1.L1 U1.L26 U1.M1 U1.M26 U1.N1 U1.N26 U1.P1 U1.P26 U1.R1 U1.R26 U1.T1 U1.T26 U1.U1 U1.U26 U1.V1 U1.V26 U1.W1 U1.W26 U1.Y1 U1.Y26

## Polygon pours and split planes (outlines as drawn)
VSSA on metal 2 "NONET_L-01_P-001" (solid, pour order 10): 1.799,2.561 1.799,2.558 1.899,2.459 1.899,1.752 1.61,1.752 1.445,2.561
VSSA on metal 2 "NONET_L-01_P-001" (solid, pour order 1): -4.653,2.095 -4.654,2.094 -4.654,1.665 -4.775,1.544 -5.237,1.544 -5.387,1.394 -5.387,0.884 -5.345,0.842 -4.83,0.842 -4.084,1.588 -4.084,2.483 -3.819,2.744 -2.541,2.744 -1.764,1.967 1.649,1.967 1.649,2.357 1.445,2.561 -1.809,2.561 -2.722,3.474 -4.653,3.474
VCC_2V5 on metal 2 "NONET_L-01_P-001" (solid, pour order 0): -6.877,1.094 -6.29,1.681 -6.29,2.963 -5.231,4.023 2.557,4.023 4.241,2.338 4.241,0.294 3.091,-0.856 2.215,-0.856 2.215,-1.378 3.468,-1.378 5.041,0.194 5.041,3.553 3.102,5.473 -6.98,5.473 -7.759,4.694 -7.759,1.094
VCC_2V5 on metal 2 "NONET_L-01_P-001" (solid, pour order 35): 1.864,2.885 1.984,2.885 2.262,2.606 2.262,1.423 2.11,1.423 2.075,1.458 2.078,1.462 2.078,2.456 1.903,2.631
VCC_2V5 on metal 2 "NONET_L-01_P-001" (solid, pour order 34): 2.138,0.262 2.701,0.262 2.709,0.254 2.709,-0.172 2.482,-0.399 2.142,-0.399
VCC_2V5 on metal 2 "NONET_L-01_P-001" (solid, pour order 12): -5.658,3.675 -2.257,3.675 -2.257,4.129 -2.324,4.196 -5.205,4.196
DVSS on metal 2 "NONET_L-01_P-001" (solid, pour order 28): -5.016,-3.169 -2.255,-3.169 -1.807,-2.641 -1.807,-2.571 -1.807,-2.038 -2.874,-2.038 -3.776,-2.94 -5.001,-2.94
DVSS on metal 2 "NONET_L-01_P-001" (solid, pour order 20): -1.807,-2.13 -1.983,-2.306 -3.142,-2.306 -2.649,-1.813 -1.66,-1.813 -1.807,-1.96
DVSS on metal 2 "NONET_L-01_P-001" (solid, pour order 27): -5.423,-0.941 -4.958,-0.941 -4.694,-0.678 -4.12,-0.104 -2.453,-0.104 -3.521,-1.172 -5.479,-1.172 -5.479,-1.078
DVSS_BOT on metal1 "NONET_L-01_P-001" (solid, pour order 24): -7.52,0.83 -7.524,0.826 -8.455,0.826 -8.455,0.999 -8.396,1.058 -6.877,1.058 -6.806,1.129 -6.806,2.095 -6.141,2.095 -6.141,0.922 -6.235,0.83 -6.251,0.83
DVDD_1V2 on metal1 "NONET_L-01_P-001" (solid, pour order 26): -5.502,0.662 -4.831,0.662 -4.778,0.715 -2.268,0.715 -2.258,0.725 -2.244,0.711 -2.244,0.214 -4.314,0.214 -4.532,0.432 -5.036,0.432
DVDD_1V2_BOT on metal1 "NONET_L-01_P-001" (solid, pour order 25): -8.338,0.433 -8.375,0.47 -8.192,0.653 -6.141,0.653 -5.966,0.828 -5.966,1.749 -5.781,1.934 -5.78,1.933 -2.257,1.933 -2.207,1.883 -2.207,1.583 -2.392,1.398 -4.027,1.398 -4.191,1.562 -5.725,1.562 -5.725,0.676 -5.946,0.433 -6.053,0.433
DVSS_BOT on metal1 "NONET_L-01_P-001" (solid, pour order 8): -2.023,2.548 -2.023,2.626 -6.529,2.626 -6.806,2.399 -6.806,2.06 -2.32,2.06

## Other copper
metal 2:
  region: 203 vertices and 1 holes, not listed, extent -2.114,-5.449 -1.673,-4.982
  region: 362 vertices and 0 holes, not listed, extent -3.251,-5.45 -2.754,-4.828
  region: 207 vertices and 1 holes, not listed, extent -0.736,-5.449 -0.298,-4.982
  region: 276 vertices and 0 holes, not listed, extent -2.736,-5.45 -2.302,-4.982
  region: 496 vertices and 2 holes, not listed, extent -4.088,-5.545 -3.4,-4.722
  region: -1.638,-5.318 -1.637,-4.995 -1.633,-4.992 -1.625,-4.99 -1.535,-4.992 -1.531,-4.995 -1.53,-5 -1.529,-5.005 -1.53,-5.043 -1.527,-5.046 -1.524,-5.045 -1.518,-5.039 -1.516,-5.038 -1.512,-5.035 -1.511,-5.033 -1.503,-5.025 -1.501,-5.024 -1.498,-5.021 -1.497,-5.019 -1.495,-5.017 -1.485,-5.012 -1.481,-5.007 -1.466,-4.999 -1.464,-4.997 -1.458,-4.995 -1.434,-4.986 -1.429,-4.985 -1.423,-4.984 -1.409,-4.983 -1.379,-4.982 -1.376,-4.984 -1.353,-4.985 -1.336,-4.993 -1.327,-4.994 -1.318,-5 -1.309,-5.005 -1.304,-5.007 -1.302,-5.01 -1.299,-5.011 -1.293,-5.017 -1.29,-5.019 -1.284,-5.025 -1.283,-5.026 -1.281,-5.028 -1.276,-5.033 -1.275,-5.035 -1.273,-5.037 -1.268,-5.045 -1.264,-5.05 -1.26,-5.057 -1.258,-5.065 -1.256,-5.066 -1.252,-5.074 -1.25,-5.083 -1.249,-5.092 -1.245,-5.105 -1.243,-5.109 -1.242,-5.117 -1.241,-5.122 -1.24,-5.143 -1.241,-5.436 -1.245,-5.44 -1.25,-5.441 -1.35,-5.44 -1.355,-5.436 -1.357,-5.428 -1.356,-5.417 -1.357,-5.167 -1.358,-5.163 -1.36,-5.148 -1.365,-5.135 -1.367,-5.13 -1.369,-5.123 -1.373,-5.117 -1.379,-5.112 -1.383,-5.104 -1.393,-5.097 -1.4,-5.093 -1.408,-5.091 -1.415,-5.09 -1.422,-5.088 -1.426,-5.087 -1.445,-5.086 -1.448,-5.087 -1.459,-5.091 -1.467,-5.092 -1.471,-5.094 -1.477,-5.099 -1.486,-5.104 -1.489,-5.107 -1.49,-5.109 -1.499,-5.118 -1.504,-5.126 -1.506,-5.129 -1.507,-5.131 -1.51,-5.136 -1.512,-5.145 -1.519,-5.16 -1.52,-5.175 -1.521,-5.196 -1.522,-5.437 -1.526,-5.441 -1.532,-5.443 -1.535,-5.441 -1.632,-5.44 -1.636,-5.437 -1.638,-5.432 -1.638,-5.319
  region: 257 vertices and 0 holes, not listed, extent -1.207,-5.45 -0.774,-4.982
  region: -2.266,-5.107 -2.267,-4.999 -2.264,-4.994 -2.262,-4.992 -2.254,-4.99 -2.154,-4.992 -2.15,-4.995 -2.149,-5.003 -2.15,-5.436 -2.154,-5.44 -2.158,-5.441 -2.262,-5.44 -2.265,-5.437 -2.267,-5.43 -2.266,-5.408 -2.266,-5.108
  region: -2.256,-4.829 -2.252,-4.825 -2.25,-4.824 -2.244,-4.821 -2.232,-4.818 -2.223,-4.816 -2.218,-4.815 -2.21,-4.813 -2.199,-4.815 -2.193,-4.817 -2.186,-4.818 -2.179,-4.82 -2.174,-4.821 -2.168,-4.823 -2.164,-4.826 -2.16,-4.83 -2.152,-4.835 -2.149,-4.838 -2.144,-4.846 -2.14,-4.85 -2.136,-4.858 -2.135,-4.865 -2.131,-4.874 -2.13,-4.879 -2.13,-4.886 -2.131,-4.889 -2.132,-4.9 -2.139,-4.919 -2.141,-4.921 -2.142,-4.923 -2.149,-4.93 -2.15,-4.932 -2.152,-4.935 -2.153,-4.936 -2.155,-4.937 -2.157,-4.94 -2.16,-4.941 -2.166,-4.946 -2.173,-4.95 -2.178,-4.951 -2.188,-4.953 -2.194,-4.954 -2.214,-4.954 -2.217,-4.953 -2.234,-4.952 -2.237,-4.951 -2.242,-4.95 -2.249,-4.947 -2.251,-4.945 -2.253,-4.944 -2.255,-4.942 -2.266,-4.936 -2.27,-4.93 -2.276,-4.923 -2.278,-4.918 -2.281,-4.91 -2.284,-4.904 -2.285,-4.9 -2.286,-4.874 -2.284,-4.868 -2.28,-4.858 -2.278,-4.852 -2.273,-4.844 -2.271,-4.843 -2.268,-4.839 -2.263,-4.833 -2.257,-4.83

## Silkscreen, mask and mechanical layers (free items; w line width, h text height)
Mechanical 1:
  lines w0.2: 2.548,6.5 -8.339,6.5 -9.2,5.639 -9.2,-6.239 -8.939,-6.5 2.548,-6.5 4.592,-6.5 4.88,-6.212 4.88,-4.161 5.241,-3.8 30.141,-3.8 31.388,-5.047 ; 2.548,6.5 4.592,6.5 4.88,6.212 4.88,4.161 5.241,3.8 30.141,3.8 31.388,5.047 31.449,5.047 36.604,5.047 37.441,4.21 37.441,-4.006 36.4,-5.047 31.449,-5.047
Document:
  text "Version = '.VersionControl_RevNumber' / Last modified = '.ModifiedDate' '.ModifiedTime'" at -81.966,-57.077 h1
